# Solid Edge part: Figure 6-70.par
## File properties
Author: Ashutosh-CADCIM
Template: Iso Metric Part.par
Last saved by: Ashutosh-CADCIM
Revision: 1
Application: Solid Edge
Accuracy: 0.990
Username: Ashutosh-CADCIM
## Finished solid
Body 1: solid body, 7 faces, 14 edges, 8 vertices.
  Faces by surface: plane 6, cylinder 1
  Edges by curve: line 12, circle 2
Bounding box of the edges (mm): 768.341 x 1086.414 x 130.000, from (-290.1106, -459.7492, -100) to (478.2308, 626.6646, 30).
Cylindrical faces by radius (mm): R64.5147 x1
Planar faces by outward normal: +x 1, +y 1, +z 1, -x 1, -y 1, -z 1
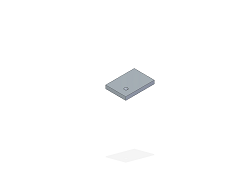
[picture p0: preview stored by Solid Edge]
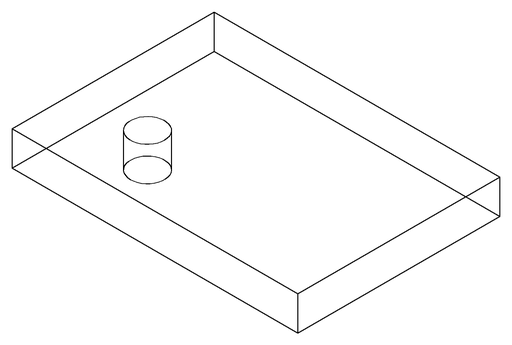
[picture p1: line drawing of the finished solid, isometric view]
